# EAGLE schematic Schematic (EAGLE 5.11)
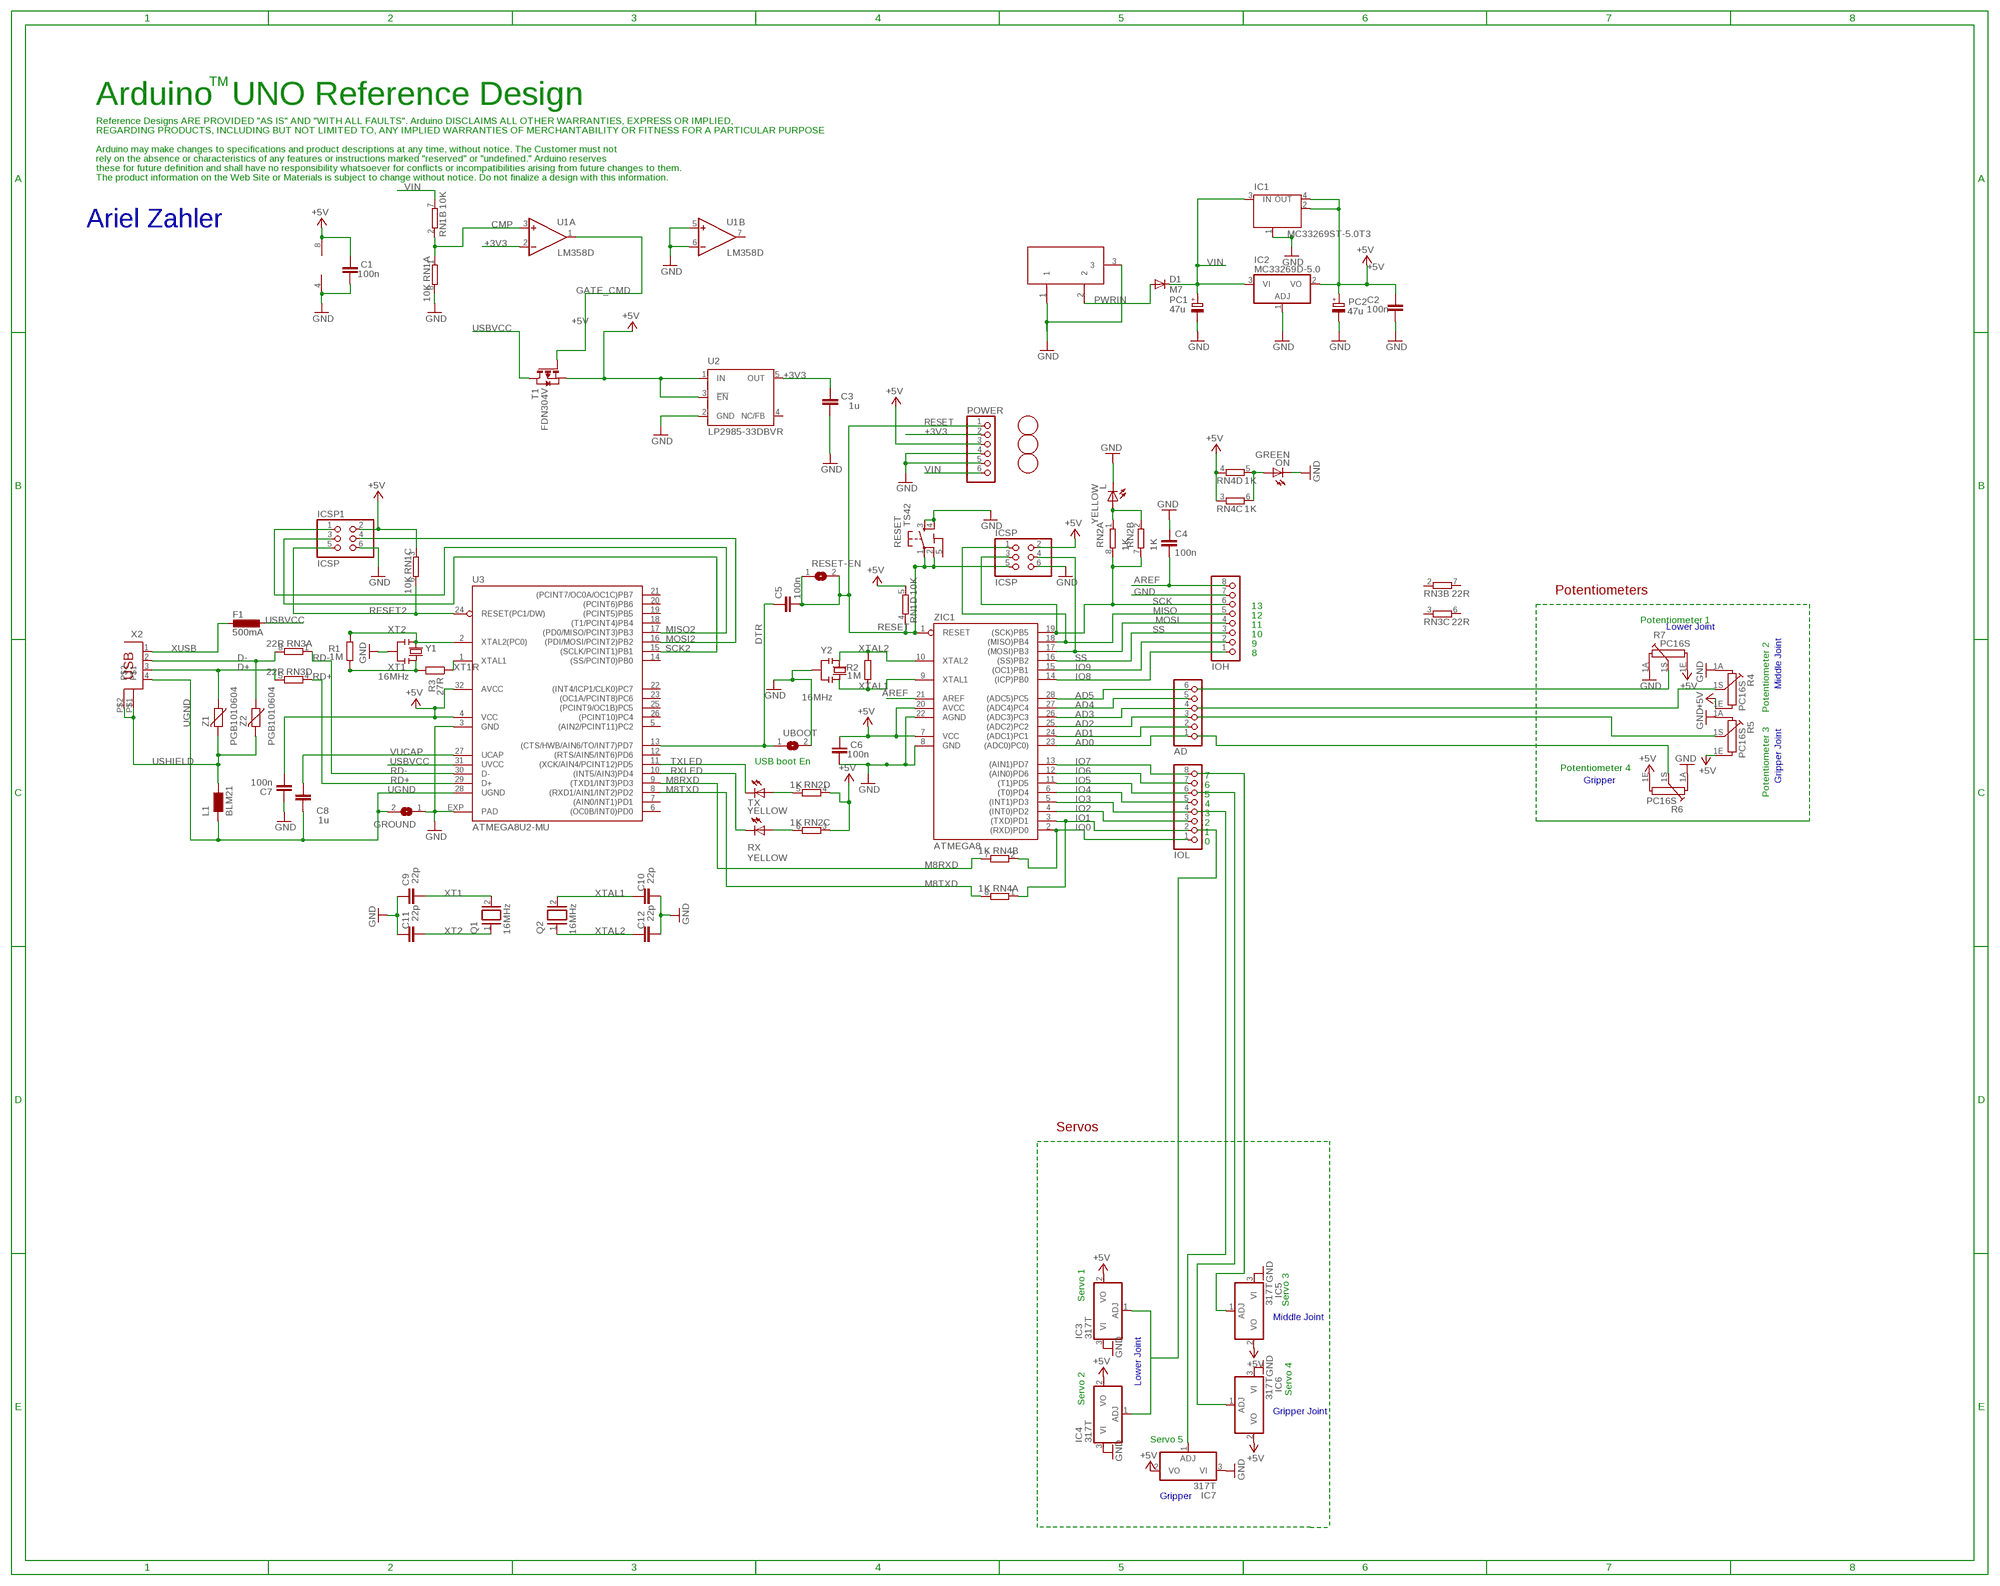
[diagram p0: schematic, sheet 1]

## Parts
AD  PINHD-1X6  [1X06]
C1  100n  C-EU0603-RND  [C0603-ROUND]
C2  100n  C-EU0603-RND  [C0603-ROUND]
C3  1u  C-EU0603-RND  [C0603-ROUND]
C4  100n  C-EU0603-RND  [C0603-ROUND]
C5  100n  C-EU0603-RND  [C0603-ROUND]
C6  100n  C-EU0603-RND  [C0603-ROUND]
C7  100n  C-EU0603-RND  [C0603-ROUND]
C8  1u  C-EU0603-RND  [C0603-ROUND]
C9  22p  C-EU0603-RND  [C0603-ROUND]
C10  22p  C-EU0603-RND  [C0603-ROUND]
C11  22p  C-EU0603-RND  [C0603-ROUND]
C12  22p  C-EU0603-RND  [C0603-ROUND]
D1  M7  DIODE-SMB  [SMB]
F1  500mA  L-EUL1812  [L1812]
GROUND  SJ  [SJ]
IC1  MC33269ST-5.0T3  MC33269ST-3.3T3  [SOT223]
IC2  MC33269D-5.0  [DPACK]
IC3  317T  [TO220H]
IC4  317T  [TO220H]
IC5  317T  [TO220H]
IC6  317T  [TO220H]
IC7  317T  [TO220H]
ICSP  ICSP  PINHD-2X3  [2X03]
ICSP1  ICSP  PINHD-2X3  [2X03]
IOH  PINHD-1X8  [1X08]
IOL  PINHD-1X8  [1X08]
L  YELLOW  LEDCHIP-LED0805  [CHIP-LED0805]
L1  BLM21  WE-CBF_0805  [0805]
ON  GREEN  LEDCHIP-LED0805  [CHIP-LED0805]
PC1  47u  CPOL-EUD  [PANASONIC_D]
PC2  47u  CPOL-EUD  [PANASONIC_D]
POWER  PINHD-1X6  [1X06]
Q1  16MHz  XTAL/S  [QS]
Q2  16MHz  XTAL/S  [QS]
R1  1M  R-EU_R0603  [R0603-ROUND]
R2  1M  R-EU_R0603  [R0603-ROUND]
R3  27R  R-EU_R0603  [R0603-ROUND]
R4  PC16S  [PC16S]
R5  PC16S  [PC16S]
R6  PC16S  [PC16S]
R7  PC16S  [PC16S]
RESET  TS42  [TS42]
RESET-EN  SJ  [SJ]
RN1  10K  4R-NCAY16  [CAY16]
RN2  1K  4R-NCAY16  [CAY16]
RN3  22R  4R-NCAY16  [CAY16]
RN4  1K  4R-NCAY16  [CAY16]
RX  YELLOW  LEDCHIP-LED0805  [CHIP-LED0805]
T1  FDN304V  PMOSSOT23  [SOT-23]
TX  YELLOW  LEDCHIP-LED0805  [CHIP-LED0805]
U1  LM358D  [SO08]
U2  LP2985-33DBVR  TPS77033  [SOT23-DBV]
U3  ATMEGA8U2-MU  [QFN32]
U$3  FIDUCIALMOUNT  [FIDUCIA-MOUNT]
U$4  FIDUCIALMOUNT  [FIDUCIA-MOUNT]
U$6  FIDUCIALMOUNT  [FIDUCIA-MOUNT]
UBOOT  SJ  [SJ]
X1  DC21MMX  [DC-21MM]
X2  PN61729  [PN61729]
Y1  16MHz  RESONATORMU  [RESONATOR]
Y2  16MHz  RESONATORMU  [RESONATOR]
Z1  PGB1010604  VARISTORCN0603  [CT/CN0603]
Z2  PGB1010604  VARISTORCN0603  [CT/CN0603]
ZIC1  ATMEGA8  AT90S4433P  [DIL28-3]

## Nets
+3V3: C3.2 POWER.2 U1.2(A:-IN) U2.5(OUT)
+5V: C1.2 C2.2 C6.2 C7.1 IC1.2(OUT) IC1.4(OUT) IC2.2(VO) IC3.2(VO) IC4.2(VO) IC5.2(VO) IC6.2(VO) IC7.2(VO) ICSP1.2 ICSP.2 PC2.+ POWER.3 R4.1E R5.1E R6.1E R7.1E RN1.3 RN1.5 RN2.3 RN2.4 RN4.3 RN4.4 T1.2(S) U1.8(P:V+) U2.1(IN) U2.3(!EN) U3.4(VCC) U3.32(AVCC) ZIC1.7(VCC) ZIC1.20(AVCC)
AD0: AD.1 ZIC1.23((ADC0)PC0))
AD1: AD.2 ZIC1.24((ADC1)PC1)
AD2: AD.3 ZIC1.25((ADC2)PC2)
AD3: AD.4 ZIC1.26((ADC3)PC3)
AD4: AD.5 ZIC1.27((ADC4)PC4)
AD5: AD.6 ZIC1.28((ADC5)PC5)
AREF: C4.2 IOH.8 ZIC1.21(AREF)
CMP: RN1.1 RN1.2 U1.3(A:+IN)
D+: RN3.5 X2.3 Z1.1
D-: RN3.8 X2.2 Z2.1
DTR: C5.1 U3.13((CTS/HWB/AIN6/TO/INT7)PD7) UBOOT.1
GATE_CMD: T1.3(G) U1.1(A:OUT)
GND: C1.1 C2.1 C3.1 C4.1 C6.1 C7.2 C9.2 C10.1 C11.2 C12.1 GROUND.1 IC1.1(GND/ADJ) IC2.1(ADJ) IC3.3(VI) IC4.3(VI) IC5.3(VI) IC6.3(VI) IC7.3(VI) ICSP1.6 ICSP.6 IOH.7 L.C ON.C PC1.- PC2.- POWER.4 POWER.5 R4.1A R5.1A R6.1A R7.1A RESET.3 RESET.4 RN1.8 U1.4(P:V-) U1.5(B:+IN) U1.6(B:-IN) U2.2(GND) U3.3(GND) U3.EXP(PAD) UBOOT.2 X1.1 X1.3 Y1.2 Y2.2 ZIC1.8(GND) ZIC1.22(AGND)
IO0: IOL.1 RN4.2 ZIC1.2((RXD)PD0)
IO1: IOL.2 RN4.1 ZIC1.3((TXD)PD1)
IO2: IOL.3 ZIC1.4((INT0)PD2)
IO3: IOL.4 ZIC1.5((INT1)PD3)
IO4: IOL.5 ZIC1.6((T0)PD4)
IO5: IOL.6 ZIC1.11((T1)PD5)
IO6: IOL.7 ZIC1.12((AIN0)PD6)
IO7: IOL.8 ZIC1.13((AIN1)PD7)
IO8: IOH.1 ZIC1.14((ICP)PB0)
IO9: IOH.2 ZIC1.15((OC1)PB1)
M8RXD: RN4.7 U3.9((TXD1/INT3)PD3)
M8TXD: RN4.8 U3.8((RXD1/AIN1/INT2)PD2)
MISO: ICSP.1 IOH.5 ZIC1.18((MISO)PB4)
MISO2: ICSP1.1 U3.17((PD0/MISO/PCINT3)PB3)
MOSI: ICSP.4 IOH.4 ZIC1.17((MOSI)PB3)
MOSI2: ICSP1.4 U3.16((PDI/MOSI/PCINT2)PB2)
N$1: IC3.1(ADJ) IC4.1(ADJ)
N$2: L.A RN2.1 RN2.2
N$3: ON.A RN4.5 RN4.6
N$4: IC7.1(ADJ)
N$5: IC6.1(ADJ)
N$6: IC5.1(ADJ)
N$8: R7.1S
N$9: R4.1S
N$10: R5.1S
N$11: R6.1S
N$35: RN2.6 RX.A
N$36: RN2.5 TX.A
PWRIN: D1.A X1.2
RD+: RN3.4 U3.29(D+)
RD-: RN3.1 U3.30(D-)
RESET: C5.2 ICSP.5 POWER.1 RESET-EN.1 RESET-EN.2 RESET.1 RESET.2 RN1.4 ZIC1.1(RESET)
RESET2: ICSP1.5 RN1.6 U3.24(RESET(PC1/DW))
RXLED: RX.C U3.10((INT5/AIN3)PD4)
SCK: ICSP.3 IOH.6 RN2.7 RN2.8 ZIC1.19((SCK)PB5)
SCK2: ICSP1.3 U3.15((SCLK/PCINT1)PB1)
SS: IOH.3 ZIC1.16((SS)PB2)
TXLED: TX.C U3.11((XCK/AIN4/PCINT12)PD5)
UGND: C8.2 GROUND.2 L1.1 U3.28(UGND) X2.4
USBVCC: F1.1 T1.1(D) U3.31(UVCC)
USHIELD: L1.2 X2.P$1 X2.P$2 Z1.2 Z2.2
VIN: D1.C IC1.3(IN) IC2.3(VI) PC1.+ POWER.6 RN1.7
VUCAP: C8.1 U3.27(UCAP)
XT1: C9.1 Q1.2 R1.1 R3.2 Y1.3
XT1R: R3.1 U3.1(XTAL1)
XT2: C11.1 Q1.1 R1.2 U3.2(XTAL2(PC0)) Y1.1
XTAL1: C10.2 Q2.2 R2.1 Y2.3 ZIC1.9(XTAL1)
XTAL2: C12.2 Q2.1 R2.2 Y2.1 ZIC1.10(XTAL2)
XUSB: F1.2 X2.1
Unconnected: RN3.2 RN3.3 RN3.6 RN3.7 U1.7(B:OUT) U2.4(NC/FB) U3.5((AIN2/PCINT11)PC2) U3.6((OC0B/INT0)PD0) U3.7((AIN0/INT1)PD1) U3.12((RTS/AIN5/INT6)PD6) U3.14((SS/PCINT0)PB0) U3.18((T1/PCINT4)PB4) U3.19((PCINT5)PB5) U3.20((PCINT6)PB6) U3.21((PCINT7/OC0A/OC1C)PB7) U3.22((INT4/ICP1/CLK0)PC7) U3.23((OC1A/PCINT8)PC6) U3.25((PCINT9/OC1B)PC5) U3.26((PCINT10)PC4)

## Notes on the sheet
- TM
- Arduino  UNO Reference Design
- Reference Designs ARE PROVIDED "AS IS" AND "WITH ALL FAULTS". Arduino DISCLAIMS ALL OTHER WARRANTIES, EXPRESS OR IMPLIED,
- REGARDING PRODUCTS, INCLUDING BUT NOT LIMITED TO, ANY IMPLIED WARRANTIES OF MERCHANTABILITY OR FITNESS FOR A PARTICULAR PURPOSE
- Arduino may make changes to specifications and product descriptions at any time, without notice. The Customer must not
- rely on the absence or characteristics of any features or instructions marked "reserved" or "undefined." Arduino reserves
- these for future definition and shall have no responsibility whatsoever for conflicts or incompatibilities arising from future changes to them.
- The product information on the Web Site or Materials is subject to change without notice. Do not finalize a design with this information.
- Ariel Zahler
- Potentiometers
- 13
- 12
- Potentiometer 1 | Lower Joint
- 11
- 10
- Potentiometer 2
- 9
- 8
- Middle Joint
- Potentiometer 3
- USB boot En | Potentiometer 4
- 7
- Gripper | Gripper Joint
- 6
- 5
- 4
- 3
- 2
- 1
- 0
- Servos
- Servo 3
- Servo 1
- Middle Joint
- Lower Joint
- Servo 4
- Servo 2
- Gripper Joint
- Servo 5
- Gripper

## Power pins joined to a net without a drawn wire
5-GND: RESET.5(5-GND)

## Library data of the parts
AD POWER = pinhead:PINHD-1X6: PIN HEADER
C1-C12 = SmartPrj:C-EU: CAPACITOR, European symbol
D1 = diode:DIODE-: DIODE
F1 = rcl:L-EU: INDUCTOR, European symbol
GROUND RESET-EN UBOOT = jumper:SJ: SMD solder JUMPER
IC1 = linear:MC33269ST*: Adjustable Output Low Dropout Voltage Regulator 800 mA Source: http://www.onsemi.com/pub/Collateral/MC33269-D.PDF
IC2 = linear:MC33269?*: Adjustable Output Low Dropout Voltage Regulator 800 mA Source: http://www.onsemi.com/pub/Collateral/MC33269-D.PDF
IC3-IC7 = linear:*317: Positive VOLTAGE REGULATOR
ICSP ICSP1 = pinhead:PINHD-2X3: PIN HEADER
IOH IOL = pinhead:PINHD-1X8: PIN HEADER
L ON RX TX = led:LED: LED
L1 = wuerth-elektronik:WE-CBF: SMD EMI Suppression Ferrite Beads
PC1 PC2 = rcl:CPOL-EU: POLARIZED CAPACITOR, European symbol
Q1 Q2 = special:XTAL/S: CRYSTAL
R1-R3 = SmartPrj:R-EU_: RESISTOR, European symbol
R4-R7 = piher:PC16S: POTENTIOMETER single carbon potentiometer, 16 mm, S3ROH; OC_FARNELL: 4452940; OC_NEWARK: unknown
RESET = st-mod v1.4:TS42: TS42 Dongnan Electronics Tact switch VDC 12V - 50mA
RN1-RN4 = resistor-dil:4R-N: Array Chip Resistor Source: RS Component / Phycomp
T1 = zetex:PMOSSOT23: MOS FET
U1 = linear:LM358: OP AMP also LM158; LM258; LM2904 Source: http://cache.national.com/ds/LM/LM158.pdf
U2 = texas:TPS770*: ULTRALOW-POWER 50-mA LOW-DROPOUT LINEAR REGULATORS 50-mA Low-Dropout Regulator Source: http://focus.ti.com/lit/ds/symlink/tps77001.pdf
U3 = atmel:ATMEGA8U2-MU
U$3 U$4 U$6 = SmartPrj:FIDUCIALMOUNT
X1 = powersupply:DC21MM
X2 = SmartPrj:PN61729: BERG USB connector
Y1 Y2 = SmartPrj:RESONATOR
Z1 Z2 = varistor:VARISTOR: VARISTOR
ZIC1 = atmel:AT90S4433: MICROCONTROLLER 4 Kbytes FLASH 128 bytes SRAM 256 bytes EEPROM UART 6-channel 10 bit ADC

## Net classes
0 default: width 0.152 mm, drill 0.305 mm, clearance 0.152 mm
